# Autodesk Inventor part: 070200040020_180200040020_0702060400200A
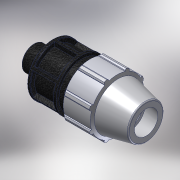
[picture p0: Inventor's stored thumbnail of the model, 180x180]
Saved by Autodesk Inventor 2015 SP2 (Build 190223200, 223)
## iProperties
Created: 2017-02
Part Number: 070200040020_180200040020_0702060400200A
Material: PVC-Piping
Description: PLASSON MALE ADAPTOR 40-2"
Document SubType Name: Modeling
Designer: KIM
Mass: 92.6774 g
Surface Area: 199.44 cm^2
Volume: 66.1981 cm^3
Density: 1.4 g/cm^3
Appearance: PTFE
Author: KIM
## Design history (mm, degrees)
derived "07020.ipt"
feature "Solid1::07020.ipt"
tag "TaggingFeature1"
body "Solid1"
other parameters: "d4" = 17.57143, "d5" = 30.75, "d7" = 82, "d8" = 61.5, "d9" = 17.57143, "d11" = 3.51429, "d12" = 65.6, "d13" = 120 deg, "d15" = 8 deg, "d16" = 73.8, "d18" = 2, "d19" = 35 deg, "d20" = 17.5 deg, "d21" = 76.26, "d23" = 0, "d25" = 360 deg, "d27" = 1.64, "d34" = 4.1, "d36" = 0, "d42" = 30.75, "d43" = 2.46, "d46" = 1.2, "d49" = 91, "d51" = 123, "d52" = 26, "d53" = 0.8, "d55" = 360 deg, "d57" = 59.614, "d58" = 35.7684, "d59" = 24.6, "E_" = 82, "H_" = 123, "l_" = 91, "l_2" = 26, "R_" = 59.614
